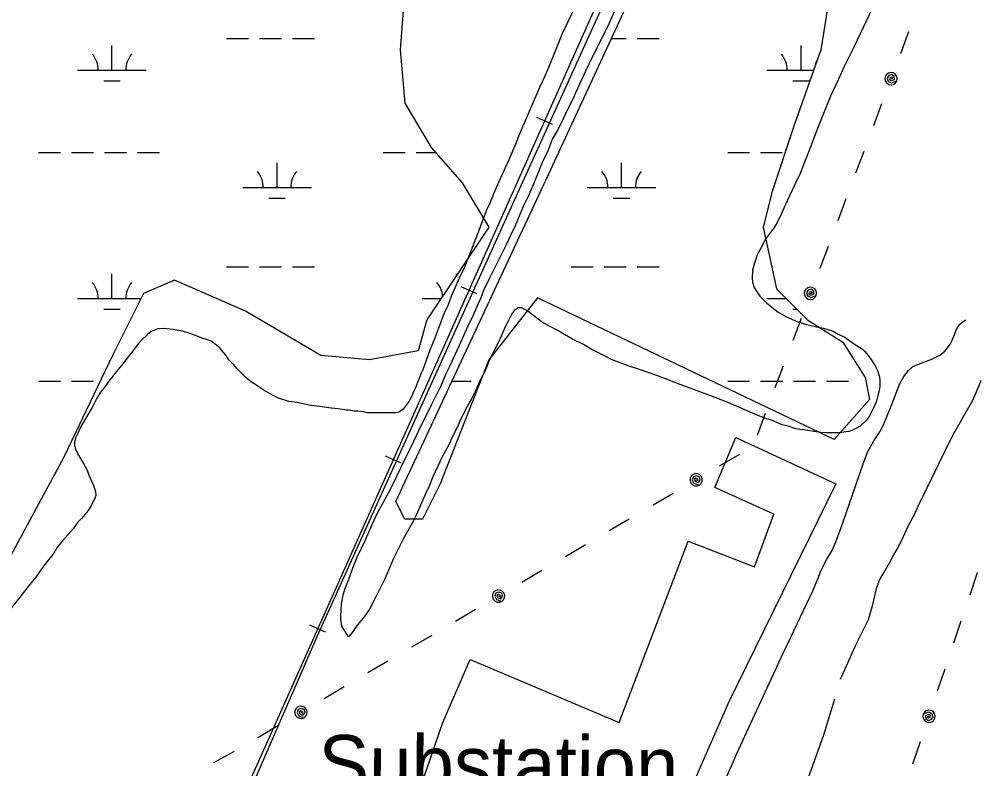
# Model space of a CAD drawing. Extents: x 3535183 to 3573198, y 534952 to 560562.
# Drawn here: x 3556701 to 3558099, y 550912 to 552004 of the extents above; entities that cross this region are included whole.
import ezdxf

# ---------------------------------------------------------------- set-up
doc = ezdxf.new("R2010")
doc.units = 0
for name, color, linetype in [('V-RAIL-TRAK', 7, 'Continuous'), ('V-ROAD-CNTR', 7, 'Continuous'), ('V-SITE-OTLN', 7, 'Continuous'), ('V-SITE-OTLN-IDEN', 7, 'Continuous'), ('V-SITE-VEGE', 7, 'Continuous'), ('V-TOPO-SHOR', 7, 'Continuous'), ('V-UTIL-LINE', 7, 'Continuous'), ('V-WETL-SWMP', 7, 'Continuous')]:
    doc.layers.add(name, color=color, linetype=linetype)

msp = doc.modelspace()

# ---------------------------------------------------------------- linework, layer by layer
at = {"layer": 'V-RAIL-TRAK'}
msp.add_lwpolyline([(3558669.1, 554106.7), (3558521.9, 553896.3), (3558296.1, 553570.3), (3558144.8, 553339.8), (3558137.4, 553327.8), (3558131.9, 553318.9), (3558126.6, 553309.9), (3558120.7, 553299.9), (3558115.1, 553289.7), (3558109.7, 553279.5), (3558104.5, 553269.1), (3558099.5, 553258.6), (3558094.7, 553248), (3558090.1, 553237.4), (3558085.7, 553226.6), (3557953.4, 552935.7), (3557765.1, 552506.1), (3557566.1, 552058.2), (3557405.5, 551703.9), (3557134.4, 551104.9), (3556938.4, 550653.4)], dxfattribs=at)
at = {"layer": 'V-ROAD-CNTR'}
for points in [[(3558071.9, 553212), (3556780.8, 550321.1), (3556216.3, 549046.1)], [(3557477.7, 551850.9), (3557454.9, 551861.1)], [(3557367.6, 551604.4), (3557344.8, 551614.6)], [(3557257.5, 551357.9), (3557234.7, 551368.1)], [(3557147.4, 551111.4), (3557124.6, 551121.5)]]:
    msp.add_lwpolyline(points, dxfattribs=at)
at = {"layer": 'V-SITE-OTLN'}
msp.add_lwpolyline([(3557318.1, 550979.9), (3557358.2, 551071.7), (3557574.8, 550979.8), (3557675.6, 551244.1), (3557772.2, 551206.7), (3557800.2, 551283.3), (3557714.6, 551322.2), (3557745, 551395.3), (3557890.4, 551327.5), (3557734.9, 551010.1), (3557631.7, 550775.2), (3557577.1, 550663.4), (3557255, 550796.2)], close=True, dxfattribs=at)
at = {"layer": 'V-SITE-VEGE'}
for points in [[(3557948.6, 552030.3), (3557916.7, 551963.6), (3557903, 551935.3), (3557894.6, 551917.1), (3557882.9, 551892.4), (3557864.8, 551847.5), (3557851.5, 551812), (3557843.4, 551792.2), (3557838.6, 551779.6), (3557832.5, 551766.7), (3557822.9, 551746.9), (3557817.2, 551734.4), (3557812, 551722.2), (3557805.1, 551708.5), (3557800.7, 551701.2), (3557793.4, 551691.5), (3557788.2, 551683.8), (3557780.9, 551670.1), (3557776.1, 551661.2), (3557771.7, 551647.8), (3557769.3, 551638.9), (3557768.9, 551627.2), (3557769.3, 551621.2), (3557771.7, 551613.5), (3557779.8, 551601), (3557789.9, 551590.9), (3557806.5, 551577.6), (3557818.6, 551570.7), (3557835.2, 551563.5), (3557846.1, 551560.2), (3557862.3, 551556.2), (3557872.8, 551554.2), (3557886.6, 551549.8), (3557894.2, 551545.8), (3557903.9, 551541.3), (3557916.5, 551532.1), (3557925.4, 551526.4), (3557929.4, 551523.6), (3557932.2, 551520.8), (3557937.5, 551514.3), (3557942, 551508.7), (3557948.4, 551498.6), (3557951.3, 551492.9), (3557954.1, 551483.6), (3557954.9, 551478), (3557954.9, 551469.5), (3557953.7, 551463.8), (3557949.7, 551448.1), (3557946.1, 551439.2), (3557944.5, 551436.3), (3557939.2, 551425.8)], [(3557510.6, 552021.9), (3557491.7, 551981.9), (3557484.9, 551965.3), (3557478, 551948.3), (3557467.1, 551922.5), (3557459.1, 551904.7), (3557448.2, 551880), (3557440.9, 551863), (3557430.1, 551838.4), (3557424, 551822.6), (3557414.4, 551799.6), (3557407.9, 551785.8), (3557401.9, 551771.7), (3557391.8, 551750.2), (3557387, 551737.3), (3557381.3, 551725.2), (3557373.3, 551704.6), (3557361.2, 551672.6), (3557348.7, 551640.7), (3557343.1, 551629.4), (3557335.4, 551612.8), (3557331, 551601.9), (3557325.3, 551586.9), (3557321.3, 551578.4)], [(3557373.8, 551599.2), (3557377.8, 551609.8), (3557385.8, 551625.5), (3557399.5, 551653.8), (3557402.4, 551659.9), (3557411.6, 551677.3), (3557416.5, 551688.6), (3557424.1, 551704), (3557435.8, 551731.9), (3557441.9, 551744.8), (3557450.7, 551764.6), (3557464.4, 551798.6), (3557470.9, 551811.5), (3557478.1, 551829.7), (3557485, 551841.8), (3557494.6, 551860.8), (3557497.5, 551866.9), (3557510, 551892.8), (3557512.4, 551898.8), (3557520.8, 551916.6), (3557526.5, 551929.1), (3557536.1, 551949.4), (3557553.5, 551984.1), (3557560.7, 551999.1), (3557571.2, 552022.5)], [(3557939.2, 551425.8), (3557934.8, 551419.8), (3557926.3, 551411.7), (3557919.9, 551408), (3557910.2, 551404), (3557905.3, 551403.2), (3557896.4, 551401.9), (3557877, 551401.9), (3557869, 551402.3), (3557858.5, 551403.9), (3557852.4, 551404.7), (3557844.7, 551406.3), (3557838.2, 551406.7), (3557832.2, 551407.9), (3557821.3, 551411.5), (3557812.4, 551413.5), (3557797.8, 551419.6), (3557788.5, 551422.8), (3557773.6, 551428.4), (3557734.8, 551445.8), (3557715, 551453.4), (3557678.2, 551466.7), (3557670.1, 551469.9), (3557629.7, 551485.6), (3557604.6, 551494.1), (3557588, 551499.3), (3557565, 551508.2), (3557552.5, 551514.6), (3557534.3, 551523.5), (3557523.3, 551530.3), (3557506.8, 551538.4), (3557483.7, 551551.7), (3557463.1, 551562.6), (3557444.5, 551577.1), (3557441.7, 551579.5), (3557432.8, 551584), (3557427.9, 551584), (3557422.3, 551579.9), (3557418.6, 551575.1), (3557413.4, 551564.6), (3557409.4, 551557.3), (3557403.3, 551542.7), (3557398.9, 551533), (3557391.2, 551517.7), (3557385.6, 551506.7), (3557378.7, 551490.2), (3557373.1, 551479.7), (3557365.8, 551463.1), (3557359.8, 551451.3), (3557353.8, 551440), (3557344.5, 551422.2), (3557338.8, 551409.7), (3557332.8, 551397.6), (3557327.2, 551385.4), (3557317.5, 551368.1), (3557303.4, 551337.7), (3557298.1, 551324.4), (3557292.5, 551311.9), (3557284.4, 551292.9), (3557279.6, 551282.8), (3557274.4, 551272.2), (3557260.7, 551248), (3557251.4, 551229.4), (3557245.8, 551217.7), (3557238.5, 551200.3), (3557233.7, 551189.4), (3557226.4, 551174.8), (3557221.2, 551163.9), (3557211.5, 551144.9), (3557203.4, 551133.6), (3557192.1, 551119.8), (3557186.5, 551111.7), (3557180.8, 551104.9), (3557171.1, 551120.2), (3557169.5, 551129.9), (3557169.5, 551135.1), (3557170.3, 551152.9), (3557173.1, 551165.5), (3557175.5, 551173.9), (3557180.7, 551187.3), (3557184, 551197), (3557189.6, 551211.1), (3557193.6, 551220.8), (3557205.3, 551245.9), (3557215.4, 551268.5), (3557223.8, 551287.1), (3557231.5, 551300.9), (3557243.2, 551322.7), (3557264.6, 551366.8), (3557272.6, 551382.6), (3557283.1, 551405.2), (3557301.6, 551442.8), (3557312.5, 551463.8), (3557315.3, 551469.5), (3557323, 551488.1), (3557329, 551499.8), (3557342.3, 551529.7), (3557355.2, 551557.6), (3557362.9, 551573.8), (3557367.7, 551584.7), (3557373.8, 551599.2)], [(3557321.3, 551578.4), (3557312, 551554.2), (3557306, 551538.8), (3557302.4, 551530.3), (3557299.2, 551522.3), (3557289.1, 551493.6), (3557286.7, 551488.7), (3557283.9, 551481), (3557281.4, 551475.4), (3557278.2, 551467.3), (3557275.8, 551462.4), (3557272.2, 551453.5), (3557269.3, 551447.9), (3557260.5, 551436.5), (3557256.8, 551433.7), (3557254, 551432.1), (3557249.6, 551430.9), (3557216.4, 551430.8), (3557208, 551431.2), (3557202.7, 551432.4), (3557194.2, 551433.6), (3557189, 551433.6), (3557180.9, 551434.8), (3557177.6, 551434.8), (3557165.5, 551436.8), (3557155.4, 551438), (3557138.8, 551440.4), (3557125.9, 551441.6), (3557105.7, 551446), (3557094, 551447.6), (3557078.6, 551452.5), (3557070.1, 551456.9), (3557057.6, 551464.2), (3557049.9, 551469), (3557039, 551476.3), (3557031.7, 551481.9), (3557023.2, 551490), (3557018, 551495.6), (3557013.5, 551500.9), (3557006.6, 551508.1), (3557002.2, 551515), (3556995.7, 551522.3), (3556993.3, 551525.5), (3556988.8, 551529.1), (3556980.7, 551535.2), (3556972.7, 551538.4), (3556969.8, 551538.8), (3556963.8, 551541.2), (3556958.1, 551543.6), (3556945.6, 551548.1), (3556936.3, 551550.5), (3556925.4, 551552.5), (3556911.2, 551553.7), (3556903.1, 551553.3), (3556893.5, 551549.6), (3556887.8, 551545.2), (3556879.7, 551537.1), (3556874.5, 551531.4), (3556866, 551520.5), (3556859.6, 551512.4), (3556849.9, 551499.9), (3556842.6, 551491), (3556831.7, 551477.2), (3556825.7, 551468.7), (3556819.6, 551461), (3556814, 551452.6), (3556807.1, 551438.8), (3556790.6, 551410.9), (3556785.8, 551400.4), (3556783.3, 551394.7), (3556781.7, 551387.5), (3556781.7, 551383.4), (3556783.8, 551375.7), (3556787.8, 551368.5), (3556794.7, 551357.2), (3556798.4, 551350.3), (3556801.2, 551344.7), (3556803.2, 551339), (3556809.3, 551325.3), (3556811.3, 551319.2), (3556812.1, 551316), (3556812.5, 551310.7), (3556811.3, 551306.7), (3556808.5, 551300.6), (3556805.7, 551295.8), (3556801.3, 551288.9), (3556791.6, 551277.2), (3556786.7, 551271.5), (3556779.5, 551262.2), (3556764.1, 551244.4), (3556756.1, 551234.3), (3556751.6, 551226.6), (3556743.6, 551216.9), (3556738.3, 551210), (3556730.7, 551199.5), (3556725.4, 551191.8), (3556712.1, 551175.6), (3556702.4, 551163.1), (3556686.7, 551143.7)]]:
    msp.add_lwpolyline(points, dxfattribs=at)
at = {"layer": 'V-TOPO-SHOR'}
for points in [[(3557691.5, 550807.8), (3557746.4, 550934.7), (3557811.1, 551074.6), (3557857.5, 551172.6), (3557864.5, 551189), (3557869.2, 551201.9), (3557877, 551216.8), (3557885.6, 551231.6), (3557891.4, 551245.7), (3557900.8, 551270.7), (3557930, 551355.4), (3557936.6, 551373.8), (3557946, 551390.2), (3557954.5, 551403.1), (3557960, 551413.6), (3557973.2, 551445.7), (3557977.9, 551458.6), (3557983.8, 551473.8), (3557989.6, 551484), (3557996.6, 551492.6), (3558002.9, 551498.4), (3558011.1, 551501.9), (3558030.6, 551509.4), (3558042.3, 551515.2), (3558049.7, 551521.5), (3558057.9, 551531.3), (3558063, 551543.8), (3558066.5, 551553.1), (3558071.2, 551560.2), (3558079.7, 551566.4)], [(3557897.5, 551043.2), (3557920.5, 551094.8), (3557938, 551130), (3557943.9, 551149.6), (3557947.4, 551164.4), (3557950.5, 551176.5), (3557954.4, 551187.1), (3557962.5, 551201.5), (3557968.4, 551211.7), (3557973.8, 551221.5), (3557980.1, 551232.4), (3557987.1, 551246.5), (3557992.9, 551259.4), (3557997.2, 551268), (3558004.6, 551282.1), (3558010.5, 551295), (3558060.4, 551397.4), (3558090, 551449.4), (3558098.2, 551467.3), (3558102.2, 551478.4)], [(3557136.6, 549160.8), (3557186, 549276.7), (3557240.6, 549412.7), (3557297.4, 549546.3), (3557354.7, 549684.7), (3557401.8, 549797.3), (3557489.4, 550016.1), (3557533, 550122.8), (3557578.6, 550231.1), (3557627.3, 550354.6), (3557687.6, 550502.3), (3557709.4, 550562.9), (3557719.2, 550585.2), (3557732, 550618.8), (3557742.5, 550646.2), (3557755, 550676.2), (3557775.6, 550722.8), (3557790.8, 550756), (3557815.4, 550810.7), (3557837.6, 550863.5), (3557873, 550962), (3557889.3, 551014.3)]]:
    msp.add_lwpolyline(points, dxfattribs=at)
at = {"layer": 'V-UTIL-LINE'}
for points in [[(3557996.6, 551986), (3557984.7, 551954.1)], [(3557971, 551917.6), (3557973.8, 551918.3), (3557972, 551919.9), (3557969.4, 551919.1), (3557968.7, 551916.3), (3557971.8, 551914.9), (3557976.1, 551916.8), (3557975.8, 551921), (3557971.9, 551923.9), (3557967.6, 551922.2), (3557965.2, 551918.5), (3557966.7, 551913.9), (3557971.8, 551911.7), (3557979.4, 551914.5), (3557980, 551917.9), (3557979.2, 551921.4), (3557977.1, 551924.2), (3557974.2, 551926.1), (3557970.7, 551926.6), (3557967.3, 551925.8), (3557964.4, 551923.8), (3557962.6, 551920.8), (3557962, 551917.3), (3557962.8, 551913.9), (3557964.9, 551911.1), (3557967.8, 551909.2), (3557971.3, 551908.6), (3557974.7, 551909.4), (3557977.6, 551911.5), (3557979.4, 551914.5)], [(3557957.3, 551881.1), (3557945.3, 551849.3)], [(3557931.3, 551811.8), (3557919.3, 551780)], [(3557905.3, 551742.6), (3557893.3, 551710.7)], [(3557879.3, 551673.3), (3557867.3, 551641.4)], [(3557853.6, 551604.9), (3557856.4, 551605.6), (3557854.7, 551607.2), (3557852, 551606.4), (3557851.3, 551603.6), (3557854.4, 551602.2), (3557858.8, 551604.1), (3557858.5, 551608.3), (3557854.5, 551611.2), (3557850.3, 551609.5), (3557847.8, 551605.8), (3557849.4, 551601.2), (3557854.4, 551599), (3557862.1, 551601.8), (3557862.6, 551605.2), (3557861.8, 551608.7), (3557859.8, 551611.5), (3557856.8, 551613.4), (3557853.3, 551613.9), (3557849.9, 551613.1), (3557847.1, 551611.1), (3557845.2, 551608.1), (3557844.7, 551604.6), (3557845.5, 551601.2), (3557847.5, 551598.4), (3557850.5, 551596.5), (3557854, 551595.9), (3557857.4, 551596.7), (3557860.2, 551598.8), (3557862.1, 551601.8)], [(3557839.9, 551568.4), (3557828, 551536.6)], [(3557813.9, 551499.1), (3557802, 551467.3)], [(3557787.9, 551429.9), (3557776, 551398)], [(3557750.1, 551370.5), (3557720.8, 551353.3)], [(3557687.2, 551333.5), (3557689.8, 551332.3), (3557689.4, 551334.6), (3557686.9, 551335.7), (3557684.5, 551333.9), (3557686.1, 551330.9), (3557690.6, 551329.6), (3557693.1, 551333.1), (3557691.8, 551337.8), (3557687.4, 551339.2), (3557683.2, 551337.8), (3557681.5, 551333.3), (3557684, 551328.4), (3557691.8, 551325.7), (3557694.4, 551328.1), (3557695.9, 551331.2), (3557696.1, 551334.7), (3557695, 551338.1), (3557692.6, 551340.7), (3557689.5, 551342.2), (3557686, 551342.4), (3557682.6, 551341.3), (3557680, 551338.9), (3557678.5, 551335.8), (3557678.3, 551332.3), (3557679.4, 551328.9), (3557681.8, 551326.3), (3557684.9, 551324.8), (3557688.4, 551324.6), (3557691.8, 551325.7)], [(3557653.6, 551313.7), (3557624.3, 551296.5)], [(3557589.8, 551276.2), (3557560.5, 551258.9)], [(3557526, 551238.7), (3557496.7, 551221.4)], [(3557462.3, 551201.1), (3557433, 551183.9)], [(3558086.1, 551166.1), (3558097, 551198.4)], [(3557399.3, 551164.1), (3557402, 551162.9), (3557401.5, 551165.2), (3557399, 551166.3), (3557396.7, 551164.5), (3557398.3, 551161.5), (3557402.8, 551160.2), (3557405.2, 551163.7), (3557404, 551168.4), (3557399.6, 551169.8), (3557395.3, 551168.4), (3557393.7, 551163.9), (3557396.2, 551159), (3557403.9, 551156.3), (3557406.5, 551158.7), (3557408.1, 551161.8), (3557408.3, 551165.4), (3557407.1, 551168.7), (3557404.8, 551171.3), (3557401.6, 551172.8), (3557398.1, 551173), (3557394.8, 551171.9), (3557392.2, 551169.5), (3557390.6, 551166.4), (3557390.4, 551162.9), (3557391.6, 551159.5), (3557393.9, 551156.9), (3557397.1, 551155.4), (3557400.6, 551155.2), (3557403.9, 551156.3)], [(3557365.7, 551144.3), (3557336.4, 551127.1)], [(3558062.5, 551096), (3558073.3, 551128.2)], [(3557302, 551106.8), (3557272.7, 551089.5)], [(3557238.2, 551069.3), (3557208.9, 551052)], [(3558038.8, 551025.9), (3558049.7, 551058.1)], [(3557174.4, 551031.7), (3557145.1, 551014.5)], [(3557111.5, 550994.7), (3557114.1, 550993.5), (3557113.7, 550995.8), (3557111.2, 550996.9), (3557108.8, 550995.1), (3557110.4, 550992.1), (3557114.9, 550990.8), (3557117.4, 550994.3), (3557116.1, 550999), (3557111.7, 551000.4), (3557107.5, 550999), (3557105.8, 550994.5), (3557108.3, 550989.6), (3557116.1, 550986.9), (3557118.7, 550989.3), (3557120.2, 550992.4), (3557120.4, 550996), (3557119.3, 550999.3), (3557116.9, 551001.9), (3557113.8, 551003.4), (3557110.2, 551003.6), (3557106.9, 551002.5), (3557104.3, 551000.1), (3557102.8, 550997), (3557102.6, 550993.5), (3557103.7, 550990.1), (3557106.1, 550987.5), (3557109.2, 550986), (3557112.7, 550985.8), (3557116.1, 550986.9)], [(3558026.3, 550989), (3558023.6, 550988.2), (3558025.4, 550986.7), (3558028, 550987.5), (3558028.6, 550990.4), (3558025.5, 550991.6), (3558021.2, 550989.6), (3558021.7, 550985.4), (3558025.7, 550982.7), (3558029.9, 550984.5), (3558032.2, 550988.3), (3558030.5, 550992.8), (3558025.4, 550994.9), (3558017.8, 550991.8), (3558017.4, 550988.4), (3558018.3, 550985), (3558020.4, 550982.2), (3558023.5, 550980.4), (3558026.9, 550980), (3558030.3, 550980.9), (3558033.1, 550983), (3558034.9, 550986.1), (3558035.3, 550989.6), (3558034.4, 550993), (3558032.3, 550995.7), (3558029.2, 550997.5), (3558025.7, 550997.9), (3558022.3, 550997), (3558019.6, 550994.9), (3558017.8, 550991.8)], [(3557077.9, 550974.9), (3557048.6, 550957.7)], [(3558003, 550919.8), (3558013.9, 550952)], [(3557014.1, 550937.5), (3556984.3, 550921)]]:
    msp.add_lwpolyline(points, dxfattribs=at)
at = {"layer": 'V-WETL-SWMP'}
for p, q in [((3557003.2, 551976.5), (3557035.2, 551976.5)), ((3557051.2, 551976.5), (3557083.2, 551976.5)), ((3557099.2, 551976.5), (3557131.2, 551976.5)), ((3557563.8, 551976.5), (3557585.1, 551976.5)), ((3557601.1, 551976.5), (3557633.1, 551976.5)), ((3556836.2, 551930), (3556836.2, 551966)), ((3557840, 551930), (3557840, 551966)), ((3556786.2, 551930), (3556886.2, 551930)), ((3557790, 551930), (3557858.3, 551930)), ((3556824.2, 551914.6), (3556848.2, 551914.6)), ((3557828, 551914.6), (3557852, 551914.6)), ((3556729.3, 551810), (3556761.3, 551810)), ((3556777.3, 551810), (3556809.3, 551810)), ((3556825.3, 551810), (3556857.3, 551810)), ((3556873.3, 551810), (3556905.3, 551810)), ((3557231.2, 551810), (3557263.2, 551810)), ((3557279.2, 551810), (3557308.1, 551810)), ((3557733.1, 551810), (3557765.1, 551810)), ((3557781.1, 551810), (3557813.1, 551810)), ((3557076.6, 551759.2), (3557076.6, 551795.2)), ((3557578.5, 551759.2), (3557578.5, 551795.2)), ((3557026.6, 551759.2), (3557126.6, 551759.2)), ((3557528.5, 551759.2), (3557628.5, 551759.2)), ((3557064.6, 551743.8), (3557088.6, 551743.8)), ((3557566.5, 551743.8), (3557590.5, 551743.8)), ((3557003.2, 551643.8), (3557035.2, 551643.8)), ((3557051.2, 551643.8), (3557083.2, 551643.8)), ((3557099.2, 551643.8), (3557131.2, 551643.8)), ((3557505.1, 551643.8), (3557537.1, 551643.8)), ((3557553.1, 551643.8), (3557585.1, 551643.8)), ((3557601.1, 551643.8), (3557633.1, 551643.8)), ((3556836.2, 551597.4), (3556836.2, 551633.4)), ((3557338.1, 551631), (3557338.1, 551633.4)), ((3556786.2, 551597.4), (3556878.5, 551597.4)), ((3557288.1, 551597.4), (3557315.6, 551597.4)), ((3557387.7, 551597.4), (3557388.1, 551597.4)), ((3557790, 551597.4), (3557818.3, 551597.4)), ((3556824.2, 551581.9), (3556848.2, 551581.9)), ((3557828, 551581.9), (3557833.7, 551581.9)), ((3556729.3, 551477.3), (3556761.3, 551477.3)), ((3556777.3, 551477.3), (3556809.3, 551477.3)), ((3557331.6, 551477.3), (3557359.2, 551477.3)), ((3557733.1, 551477.3), (3557765.1, 551477.3)), ((3557781.1, 551477.3), (3557813.1, 551477.3)), ((3557829.1, 551477.3), (3557861.1, 551477.3)), ((3557877.1, 551477.3), (3557909.1, 551477.3))]:
    msp.add_line(p, q, dxfattribs=at)
for points in [[(3557959, 553049.2), (3557765.6, 552617.2), (3557733.3, 552578.5), (3557643.1, 552443.1), (3557546.4, 552359.3), (3557398.1, 552236.8), (3557307.8, 552133.7), (3557262.7, 552049.8), (3557256.2, 551959.6), (3557262.7, 551882.2), (3557301.4, 551817.7), (3557346.5, 551766.1), (3557385.2, 551701.7), (3557294.9, 551566.3), (3557282, 551521.1), (3557211.1, 551508.2), (3557140.2, 551514.7), (3557030.6, 551579.2), (3556927.4, 551624.3), (3556882.3, 551605), (3556837.1, 551514.7), (3556766.2, 551366.4), (3556675.9, 551198.8)], [(3557894.5, 552120.8), (3557868.7, 551959.6), (3557830.1, 551850), (3557797.8, 551753.2), (3557784.9, 551701.7), (3557804.3, 551611.4), (3557823.6, 551592.1), (3557849.4, 551566.3), (3557901, 551534), (3557933.2, 551482.4), (3557939.7, 551450.2), (3557888.1, 551392.2), (3557456.1, 551598.5), (3557385.2, 551508.2), (3557314.3, 551327.7), (3557288.5, 551276.1), (3557262.7, 551276.1), (3557249.8, 551301.9), (3557475.4, 551785.5), (3557875.2, 552649.5)]]:
    msp.add_lwpolyline(points, dxfattribs=at)
for centre, start, end in [((3556780.9, 551930.5), 359.2282, 40.7718), ((3556891.4, 551930.5), 139.2282, 180.7718), ((3557784.7, 551930.5), 359.2282, 40.7718), ((3557895.2, 551930.5), 149.893, 171.2264), ((3557021.4, 551759.7), 359.2282, 40.7718), ((3557131.9, 551759.7), 139.2282, 180.7718), ((3557523.3, 551759.7), 359.2282, 40.7718), ((3557633.8, 551759.7), 139.2282, 180.7718), ((3556780.9, 551597.8), 359.2282, 40.7718), ((3556891.4, 551597.8), 139.2282, 180.7718), ((3557282.8, 551597.8), 4.8516, 40.7718)]:
    msp.add_arc(centre, 35.2, start, end, dxfattribs=at)

# ---------------------------------------------------------------- texts
at = {"layer": 'V-SITE-OTLN-IDEN'}
msp.add_text('Substation', height=83, rotation=359.663, dxfattribs=at).set_placement((3557136.6, 550878.8))

doc.saveas('drawing.dxf')
